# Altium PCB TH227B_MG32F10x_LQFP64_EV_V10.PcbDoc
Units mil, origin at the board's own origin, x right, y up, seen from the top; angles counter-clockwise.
Board outline 3031.5 x 2165.35 mil, 2 copper layers (Top Layer, Bottom Layer); 45 components, 67 nets, 247 pads, 62 vias.
Unrouted connection lines stored in the file: 6.
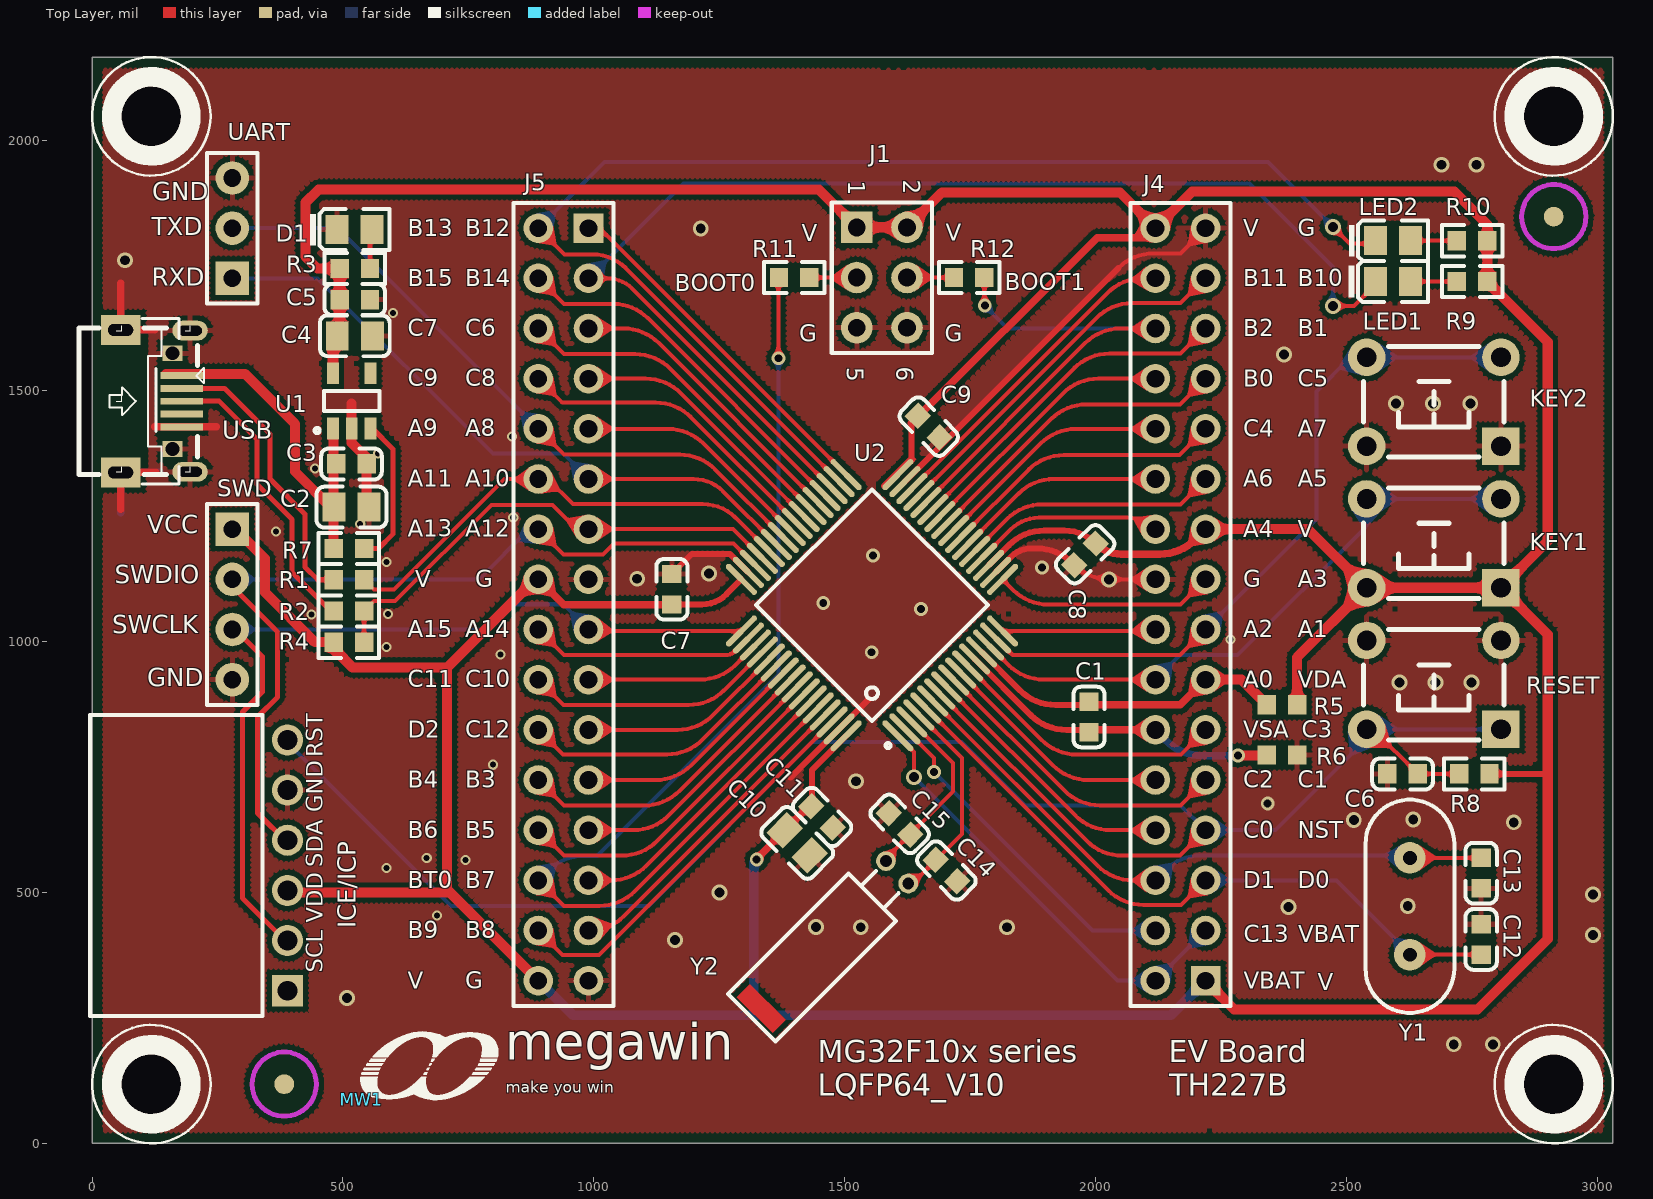
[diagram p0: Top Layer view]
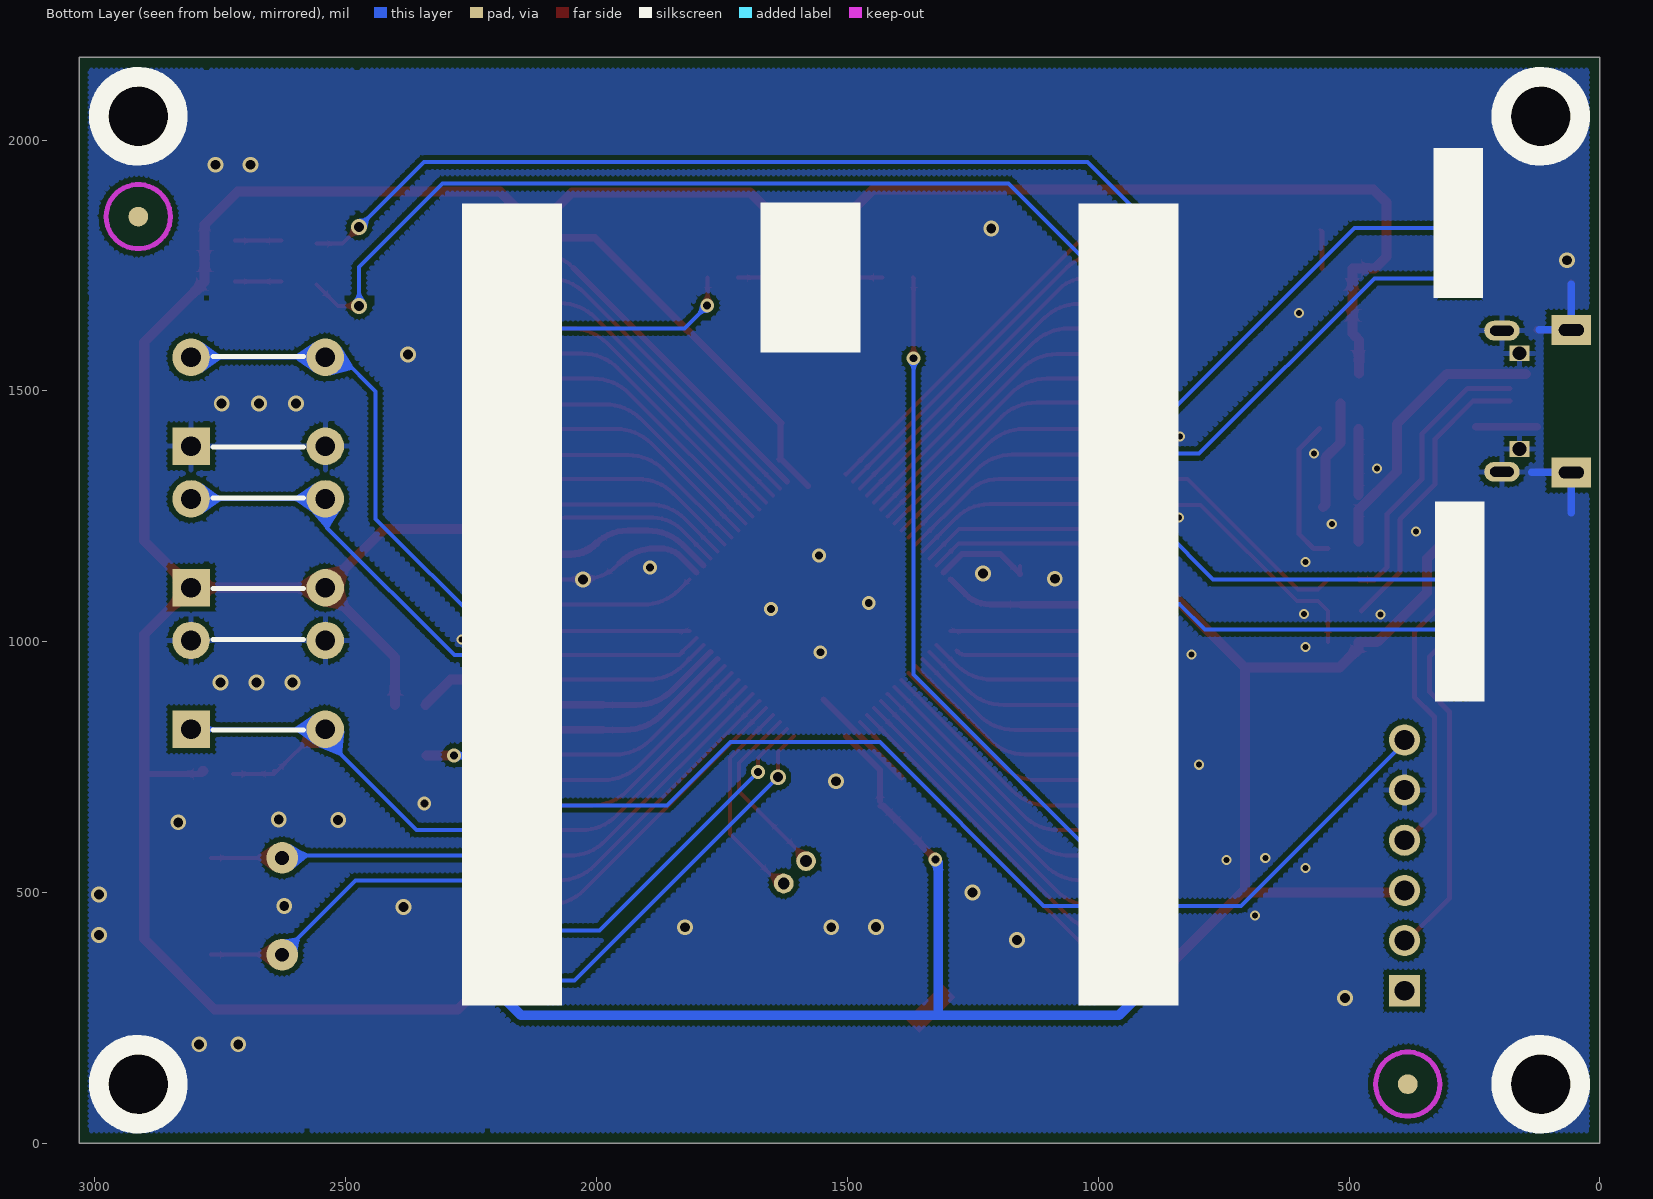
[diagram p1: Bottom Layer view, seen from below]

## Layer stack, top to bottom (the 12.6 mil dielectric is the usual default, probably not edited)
Top Layer: signal copper 1.4
Dielectric: dielectric 12.6, FR-4, Dk 4.8
Bottom Layer: signal copper 1.4

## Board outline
0,0 3031.5,0 3031.5,2165.35 0,2165.35

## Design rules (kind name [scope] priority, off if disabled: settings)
Clearance 10 [All] p1 off: gap=10
Clearance 6 [All] p2: gap=6
HoleSize [All] p1: absolutevalues=TRUE maxlimit=300 minlimit=1 maxpercent=80.000 minpercent=20.000
PolygonConnect "via Direct" [isvia] p1: connectstyle=Direct reliefconductorwidth=10 reliefentries=4 polygonreliefangle="90 Angle"
PolygonConnect "Relief 15" [isvia] p2: connectstyle=Relief reliefconductorwidth=15 reliefentries=4 polygonreliefangle="90 Angle"
RoomDefinition TH227B_MG32F10x_LQFP64_EV_V10 [InComponentClass('TH227B_MG32F10x_LQFP64_EV_V10')] p1: confinementstyle=ConfineIn formatcopy=TRUE lockcomponents=FALSE outline -120,-195 3150,-195 3150,2245 -120,2245
RoutingVias [All] p1: holewidth=15.75 width=27.56 viastyle="Through Hole" minholewidth=11.81 minwidth=23.62 maxholewidth=28 maxwidth=50
SilkscreenOverComponentPads SilkToSolderMaskClearance [IsPad] p1: minsilkscreentomaskgap=10
SolderMaskExpansion [All] p1: expansion=4
Width [All] p1: maxlimit=100 minlimit=6 preferedwidth=10 minimp=50.000000 maximp=50.000000 favimp=50.000000
26 further rules are at their usual default settings.

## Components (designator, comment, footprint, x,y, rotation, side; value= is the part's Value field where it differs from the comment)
C1 "0.1uF" 0603_C 1987.15,850 r270 top
C2 "10uF" 0805_C 517.15,1268.2 r0 top
C3 "0.1uF" 0603_C 517.15,1354.43 r0 top
C4 "10uF" 0805_C 523.8,1609.75 r0 top
C5 "0.1uF" 0603_C 523.8,1681.79 r0 top
C6 "0.1uF" 0603_C 2612.13,736.48 r180 top
C7 "0.1uF" 0603_C 1155.75,1104.62 r90 top
C8 "0.1uF" 0603_C 1979.37,1174.31 r225 top
C9 "0.1uF" 0603_C 1667.72,1428.74 r315 top
C10 "10uF" 0805_C 1405.44,599.08 r315 top
C11 "0.1uF" 0603_C 1455.12,650.65 r315 top
C12 "20pF" 0603_C 2768.9,406.56 r90 top
C13 "20pF" 0603_C 2768.9,538.84 r270 top
C14 "12pF" 0603_C 1702.79,543.96 r315 top
C15 "12pF" 0603_C 1609.81,636.94 r135 top
D1 "" 0805_LED_S1 523.23,1821.32 r0 top
ICE/ICP "" PS6P254F_90 389.61,304.31 r90 top (schematic designator J8)
J1 "CON3X2" HDR-3X2 1524.41,1825.85 r270 top (schematic designator JP1)
J4 "CON16X2" HDR2X16_MR#1 2219.53,324.31 r180 top (schematic designator P1)
J5 "CON16X2" HDR2X16_MR#2 989.61,1824.31 r180 top locked (schematic designator P2)
KEY1 "SW-PB4" "TSW DIP-6*6*6"#1 2674.41,1196.12 r180 top
KEY2 "SW-PB4" "TSW DIP-6*6*6"#1 2674.41,1478.21 r180 top
LED1 "" 0805_LED_S1 2593.21,1717.97 r0 top
LED2 "" 0805_LED_S1 2593.31,1799.27 r0 top (schematic designator LED1)
MW1 "MW-A4" MEGAWIN_3.4 537.8,86.83 r0 top
R1 "33" 0603_R 511.93,1123.53 r0 top
R2 "33" 0603_R 511.93,1061.32 r0 top
R3 "4.7k" 0603_R 523.8,1744 r0 top
R4 "1.5k" 0603_R 511.93,999.12 r180 top
R5 "0" 0603_R 2371.65,874.27 r180 top
R6 "0" 0603_R 2371.65,774.27 r180 top
R7 "0" 0603_R 511.93,1185.73 r0 top
R8 "10k" 0603_R 2755.12,736.48 r180 top
R9 "4.7k" 0603_R 2750.83,1717.97 r180 top
R10 "4.7k" 0603_R 2750.83,1799.27 r180 top
R11 "10k" 0603_R 1399.61,1725.85 r0 top
R12 "10k" 0603_R 1748.43,1725.85 r0 top
RESET "SW-PB4" "TSW DIP-6*6*6"#2 2674.41,914.04 r180 top
SWD "CON4" HDR-1X4 279.61,1224.31 r270 top
U1 "SPX3819M5-L-3-3" SOT-23-5 517.6,1479.96 r270 top
U2 "MG32F10x" LQFP64 1554.62,1072.77 r135 top locked
UART "CON3" HDR-1X3 279.61,1724.31 r90 top
USB "MICRO_USB" USB5-micro_B-建倚MRUSB-5B-D17xx- 167.96,1479.36 r270 top
Y1 "8MHz" LC-HC-49S 2626.69,472.7 r90 top
Y2 "32.768MHz" XTAL-3X8H 1604.67,540.4 r225 top

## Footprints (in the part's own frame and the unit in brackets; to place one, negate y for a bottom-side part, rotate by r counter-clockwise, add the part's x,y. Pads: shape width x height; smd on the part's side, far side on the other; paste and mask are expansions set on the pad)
0603_C [mm]
  rect 0.93x0.98 smd: 1(-0.77,0) 2(0.77,0)
  silkscreen extent -1.53,-0.79 1.54,0.79, body extent -0.8,-0.4 0.8,0.4, height 0.3
0603_R [mm]
  rect 0.93x0.98 smd: 1(-0.77,0) 2(0.77,0)
  silkscreen extent -1.53,-0.79 1.54,0.79, body extent -0.85,-0.4 0.85,0.4, height 0.56
0805_C [mm]
  rect 1.16x1.47 smd: 1(-0.89,0) 2(0.89,0)
  silkscreen extent -1.77,-1.04 1.77,1.04, body extent -1,-0.63 1,0.63, height 0.77
0805_LED_S1 [mm]
  rect 1.16x1.47 smd: 1(0.89,0) 2(-0.89,0)
  silkscreen extent -2.25,-1.04 1.77,1.03, body extent -1.01,-0.63 1.01,0.62, height 1.1
HDR2X16_MR#1 [mm] "Connector; Header; 16x2 Position"
  rect 1.5x1.5 hole 0.9: 1(0,0)
  round 1.5 hole 0.9: 2(2.54,0) 3(0,-2.54) 4(2.54,-2.54) 5(0,-5.08) 6(2.54,-5.08) 7(0,-7.62) 8(2.54,-7.62) 9(0,-10.16) 10(2.54,-10.16) 11(0,-12.7) 12(2.54,-12.7) 13(0,-15.24) 14(2.54,-15.24) 15(0,-17.78) 16(2.54,-17.78) 17(0,-20.32) 18(2.54,-20.32) 19(0,-22.86) 20(2.54,-22.86) 21(0,-25.4) 22(2.54,-25.4) 23(0,-27.94) 24(2.54,-27.94) 25(0,-30.48) 26(2.54,-30.48) 27(0,-33.02) 28(2.54,-33.02) 29(0,-35.56) 30(2.54,-35.56) 31(0,-38.1) 32(2.54,-38.1)
  silkscreen extent -1.27,-39.37 3.81,1.27
HDR2X16_MR#2 [mm] "Connector; Header; 16x2 Position"
  rect 1.5x1.5 hole 0.9: 1(0,0)
  round 1.5 hole 0.9: 2(2.54,0) 3(0,2.54) 4(2.54,2.54) 5(0,5.08) 6(2.54,5.08) 7(0,7.62) 8(2.54,7.62) 9(0,10.16) 10(2.54,10.16) 11(0,12.7) 12(2.54,12.7) 13(0,15.24) 14(2.54,15.24) 15(0,17.78) 16(2.54,17.78) 17(0,20.32) 18(2.54,20.32) 19(0,22.86) 20(2.54,22.86) 21(0,25.4) 22(2.54,25.4) 23(0,27.94) 24(2.54,27.94) 25(0,30.48) 26(2.54,30.48) 27(0,33.02) 28(2.54,33.02) 29(0,35.56) 30(2.54,35.56) 31(0,38.1) 32(2.54,38.1)
  silkscreen extent -1.27,-1.27 3.81,39.37
HDR-1X3 [mm] "齬渀ㄛ3褐"
  rect 1.7x1.7 hole 0.9: 1(0,0)
  round 1.7 hole 0.9: 2(2.54,0) 3(5.08,0)
  silkscreen extent -1.27,-1.27 6.35,1.27, body extent -1.27,-1.27 6.35,1.27, height 8.5
HDR-1X4 [mm] "齬渀ㄛ4褐"
  rect 1.7x1.7 hole 0.9: 1(0,0)
  round 1.7 hole 0.9: 2(2.54,0) 3(5.08,0) 4(7.62,0)
  silkscreen extent -1.27,-1.27 8.89,1.27, body extent -1.27,-1.27 8.89,1.27, height 8.5
HDR-3X2 [mm] "邧齬齬渀ㄛ3x2褐"
  rect 1.6x1.6 hole 0.9: 1(0,0)
  round 1.6 hole 0.9: 2(0,2.54) 3(2.54,0) 4(2.54,2.54) 5(5.08,0) 6(5.08,2.54)
  silkscreen extent -1.27,-1.27 6.35,3.81, body extent -1.27,-1.27 6.35,3.81, height 8.5
LC-HC-49S [mm]
  round 1.6 hole 0.7: 1(-2.45,0) 2(2.45,0)
  silkscreen extent -5.39,-2.25 5.39,2.25, body extent -5.39,-2.27 5.41,2.23, height 3.6
LQFP64 [mm]
  oval 2.1x0.3 smd: 1(-5.6,3.75) 2(-5.6,3.25) 3(-5.6,2.75) 4(-5.6,2.25) 5(-5.6,1.75) 6(-5.6,1.25) 7(-5.6,0.75) 8(-5.6,0.25) 9(-5.6,-0.25) 10(-5.6,-0.75) 11(-5.6,-1.25) 12(-5.6,-1.75) 13(-5.6,-2.25) 14(-5.6,-2.75) 15(-5.6,-3.25) 16(-5.6,-3.75) 33(5.6,-3.75) 34(5.6,-3.25) 35(5.6,-2.75) 36(5.6,-2.25) 37(5.6,-1.75) 38(5.6,-1.25) 39(5.6,-0.75) 40(5.6,-0.25) 41(5.6,0.25) 42(5.6,0.75) 43(5.6,1.25) 44(5.6,1.75) 45(5.6,2.25) 46(5.6,2.75) 47(5.6,3.25) 48(5.6,3.75)
  oval 0.3x2.1 smd: 17(-3.75,-5.6) 18(-3.25,-5.6) 19(-2.75,-5.6) 20(-2.25,-5.6) 21(-1.75,-5.6) 22(-1.25,-5.6) 23(-0.75,-5.6) 24(-0.25,-5.6) 25(0.25,-5.6) 26(0.75,-5.6) 27(1.25,-5.6) 28(1.75,-5.6) 29(2.25,-5.6) 30(2.75,-5.6) 31(3.25,-5.6) 32(3.75,-5.6) 49(3.75,5.6) 50(3.25,5.6) 51(2.75,5.6) 52(2.25,5.6) 53(1.75,5.6) 54(1.25,5.6) 55(0.75,5.6) 56(0.25,5.6) 57(-0.25,5.6) 58(-0.75,5.6) 59(-1.25,5.6) 60(-1.75,5.6) 61(-2.25,5.6) 62(-2.75,5.6) 63(-3.25,5.6) 64(-3.75,5.6)
  silkscreen extent -5.72,-4.15 4.15,4.57
MEGAWIN_3.4 [mil]
  silkscreen extent -2,0 272,135
PS6P254F_90 [mil]
  rect 62x62 hole 39.37: 1(0,0)
  round 62 hole 39.37: 2(100,0) 3(200,0) 4(300,0) 5(400,0) 6(500,0)
  silkscreen extent -50,50 550,394
SOT-23-5 [mm]
  rect 1.1x0.6 smd: 1(1.4,-0.95) 2(1.4,0) 3(1.4,0.95) 4(-1.4,0.95) 5(-1.4,-0.95)
  silkscreen extent -0.5,-1.87 1.62,1.4
"TSW DIP-6*6*6"#1 [mm] "6*6*6mm"
  rect 1.9x1.9 hole 1: 1(-3.4,2.25)
  round 1.9 hole 1: 2(3.4,2.25) 3(3.4,-2.25) 4(-3.4,-2.25)
  silkscreen extent -3.56,-2.79 3.56,2.79, body extent -4.11,-3 4.11,3, height 5.95
"TSW DIP-6*6*6"#2 [mm] "6*6*6mm"
  round 1.9 hole 1: 1(3.4,-2.25) 2(-3.4,-2.25) 4(3.4,2.25)
  rect 1.9x1.9 hole 1: 3(-3.4,2.25)
  silkscreen extent -3.56,-2.79 3.56,2.79, body extent -4.11,-3 4.11,3, height 5.95
USB5-micro_B-建倚MRUSB-5B-D17xx- [mm]
  rect 0.35x2.159 smd: 1(-1.3,0.279) 2(-0.65,0.279) 3(0,0.279) 4(0.65,0.279) 5(1.3,0.279)
  rect 0.8x1 hole 0.7: 5(-2.425,-0.19) 5(2.425,-0.19)
  oval 1x1.8 hole 0.5 slot 1.2 at 90 deg: 6(3.576,0.697) 9(-3.574,0.697)
  rect 1.5x2 hole 0.6 slot 1.27 at 90 deg: 7(3.607,-2.819) 8(-3.607,-2.819)
  silkscreen extent -4.19,-4.92 4.19,1.4, body extent -4,-5.61 4,-0.01, height 2.8
XTAL-3X8H [mm]
  round 1 hole 0.6: 1(0,-0.8) 2(0,0.8)
  silkscreen extent 0.7,-1.7 10.41,1.7

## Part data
C1 C2 C3 C4 C5 C6 C7 C8 C9 C10 C11 C12 C13 C14 C15: library part CAP, "Capacitor"
D1 LED1 LED2: library part LED_SC
ICE/ICP: library part CON6, "Connector"
MW1: library part MW_A4
R1 R2 R3 R4 R5 R6 R7 R8 R9 R10 R11 R12: library part RES1
SWD UART: "Connector"
U1: library part IC5_SPX3819M5-L-3-3
U2: library part IC64_MG32F10x
USB: library part USB_Micro
Y1 Y2: library part XTAL, "Crystal"

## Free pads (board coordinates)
  round 125.98 hole 118.11: 0(118.11,118.12) 0(118.12,2047.25) 0(2913.38,118.11) 0(2913.39,2047.24)
  round 39.37 smd mask+39.37: 0(383.11,118.12) 0(2913.39,1847.24)
  round 39.37 smd far side mask+39.37: 0(383.11,118.12) 0(2913.39,1847.24)

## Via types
v1: diameter 31.5, hole 19.68, Top Layer to Bottom Layer, tented both sides, 33 vias
v2: diameter 20, hole 12, Top Layer to Bottom Layer, tented both sides, 18 vias
v3: diameter 27.56, hole 15.75, Top Layer to Bottom Layer, tented both sides, 11 vias

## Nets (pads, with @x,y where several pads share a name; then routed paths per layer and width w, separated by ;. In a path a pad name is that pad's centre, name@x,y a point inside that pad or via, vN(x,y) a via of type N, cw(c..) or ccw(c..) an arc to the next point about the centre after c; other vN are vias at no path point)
BOOT0: J5.28 R11.1 U2.60 | length 2162.8
  Top Layer w8: J5.28@897.58,516.34 940.39,473.52 1011.39,473.52 ccw(c1011.39,573.52) 1082.1,502.81 U2.60 ; v3(1368.11,1565) 1368.11,1723.88 1367.72,1724.27 R11.1
  Bottom Layer w8: J5.28 909.1,543.8 cw(c979.81,473.09) 979.81,573.09 1006.24,573.09 1368.11,934.96 v3(1368.11,1565)
D+: R2.1 USB.3 | length 584.5
  Top Layer w10: USB.3@178.96,1479.35 253.36,1479.35 329.01,1403.7 329.01,1313.7 399.01,1243.7 399.01,1137.94 R2.1@475.62,1061.32
D-: R1.1 USB.2 | length 579.1
  Top Layer w8: R1.1 478.94,1123.53 480.28,1124.86 R1.1@481.61,1126.2
  Top Layer w10: USB.2 263.96,1504.95 354.61,1414.31 354.61,1324.31 424.61,1254.31 424.61,1148.54 449.62,1123.53 R1.1@478.94,1123.53
GND_POWER: C2.2 C3.2 C4.2 C5.2 C6.2 C7.2 C8.2 C9.2 C10.2 C11.2 C12.2 C13.2 C14.2 C15.2 D1.2 ICE/ICP.5 J1.5 J1.6 J4.18 J4.31 J5.15 J5.31 KEY2.1 KEY2.2 R6.1 RESET.1 RESET.2 SWD.4 U1.2 U2.18 U2.31 U2.47 U2.63 UART.3 USB.5 USB.6 USB.7 USB.8 USB.9 | length 2553.9
  Top Layer w8: J5.15@999.94,1124.31 J5.15@1010.57,1134.94 ; C7.2 C7.2@1155.75,1151.21 ; U2.47@1308.13,1138.19 U2.47 ; C8.2@1954.01,1156.8 C8.2 ccw(c2026.9,1221.83) v1(2026.9,1124.31) J4.18 ; 2045.53,1744.62 cw(c2116.24,1673.91) 2116.24,1773.91 2169.13,1773.91 J4.31
  Top Layer w12: C7.2 1195.8,1174.99 1271.32,1174.99 U2.47@1308.13,1138.19 ; 1391.75,728.95 1547.31,884.5 ; U2.31 2045.53,1744.62 ; U2.18 1832.25,1169.44 cw(c1872.44,1129.23) 1872.44,1186.08 1883.3,1186.08 cw(c1883.3,1086.08) C8.2@1954.01,1156.8
  Top Layer w15: 56.96,1264.49 USB.7 127.16,1337.36 ; 56.96,1714.12 USB.8 125.1,1621.36 ; 124.83,1428.17 247.15,1428.17
  Top Layer w20: 517.6,1474.31 517.6,1396.32 547.46,1366.45 C3.2 547.46,1272.93 C2.2
  Bottom Layer w15: 56.96,1257.16 USB.7 135.9,1337.36 ; 56.96,1712.16 USB.8 121.16,1621.36
  other v1: 2714.06,197.5 2792.09,197.5 508.15,290 1161.81,405.77 2991.73,415.22 1532.28,430.86 1824.02,430.86 1443.31,431.36 2385.04,471.52 2622.44,473.09 2991.73,496.32 1250.79,500.26 2833.86,640.02 2515,644.81 2633.47,645.93 1522.49,721.91 2606.3,918.41 2677.95,918.41 2749.61,918.41 1086.61,1125.46 1229.53,1136.09 2598.82,1475.06 2673.03,1475.06 2747.25,1475.06 2375.99,1572.31 65.63,1760.22 1213.39,1823.88 2689.75,1950.65 2759.45,1950.65
  other v2: 687.15,454.31 587.15,549.31 744.61,564.81 667.15,569.31 799.61,754.81 814.61,974.81 587.15,989.31 2269.61,1004.81 437.15,1054.31 589.61,1054.81 587.15,1159.31 367.15,1219.31 534.61,1234.81 839.61,1247.86 444.61,1344.81 569.61,1374.81 837.15,1409.31 599.61,1654.81
  other v3: 2343.31,677.82 1554,979 1652.36,1065.22 1457.48,1077.03 1893.31,1147.9 1556.69,1171.52
NetD1_1: D1.1 R3.2 | length 79
  Top Layer w6: D1.1@554.11,1817.16 D1.1
  Top Layer w10: R3.2 D1.1@554.11,1817.16
NetJ1_3: J1.3 R11.2 | length 94.5
  Top Layer w8: R11.2 J1.3
NetJ1_4: J1.4 R12.1 | length 93.7
  Top Layer w8: J1.4 R12.1
NetLED1_1: LED1.1 R9.2 | length 92.3
  Top Layer w7.87: LED1.1 R9.2
NetLED2_1: LED2.1 R10.2 | length 92.2
  Top Layer w8: LED2.1 R10.2
NetR7_2: R7.2 U1.3 | length 296.5
  Top Layer w10: R7.2 571.03,1185.73 599.61,1214.31 599.61,1384.31 U1.3@559.07,1424.84
NRST: C6.1 ICE/ICP.6 J4.7 R8.2 RESET.3 RESET.4 U2.7 | length 3743.6
  Top Layer w8: U2.7 1982.82,602.81 ccw(c2053.53,673.52) 2053.53,573.52 2168.74,573.52 J4.7@2207.78,612.56 ; RESET.4 2553.47,825.45 C6.1 R8.2 ; C6.1@2640.79,741.99 C6.1@2642.44,741.99
  Bottom Layer w8: ICE/ICP.6@388.94,799.78 715.21,473.52 1108.82,473.52 1435.3,800 1733.15,800 1859.24,673.91 2169.92,673.91 J4.7 2359,624.31 2540.55,805.86 RESET.4 RESET.3
PA0: J4.14 KEY1.3 KEY1.4 U2.14 | length 1252.4
  Top Layer w8: U2.14 1826.9,953.6 ccw(c1897.62,1024.31) 1897.62,924.31 J4.14
  Bottom Layer w8: J4.14 2168.71,973.49 2283.46,973.49 2537.11,1227.13 2537.11,1284.71 KEY1.3@2537.11,1311.98 ; KEY1.3 KEY1.4
PA1: J4.15 KEY2.3 KEY2.4 U2.15 | length 1416.2
  Top Layer w8: U2.15 1835.21,973.13 2168.35,973.13 J4.15
  Bottom Layer w8: J4.15 2440.16,1244.94 2440.16,1499.08 2507.88,1566.79 KEY2.3 KEY2.4
PA2: J4.16 U2.16 | length 305.9
  Top Layer w8: U2.16 2116.48,1021.26 J4.16
PA3: J4.17 U2.17 | length 442
  Top Layer w8: U2.17 1835.98,1103.2 ccw(c1906.69,1173.91) 1906.69,1073.91 2169.13,1073.91 J4.17
PA4: J4.20 U2.20 | length 382.6
  Top Layer w8: U2.20 1830.47,1223.34 ; 1830.49,1223.36 cw(c1887.94,1165.86) 1887.94,1247.14 2064.4,1247.14 cw(c2064.4,1169.18) 2119.49,1224.34 cw(c2064.4,1169.18) J4.20
PA5: J4.21 U2.21 | length 515.8
  Top Layer w8: U2.21 1823.92,1244.62 cw(c1894.63,1173.91) 1894.63,1273.91 2169.13,1273.91 J4.21
PA6: J4.22 U2.22 | length 423.9
  Top Layer w8: U2.22 1846.47,1295.02 cw(c1917.18,1224.31) 1917.18,1324.31 J4.22
PA7: J4.23 U2.23 | length 573.5
  Top Layer w8: U2.23 1866.27,1342.66 cw(c1936.98,1271.94) 1936.98,1371.94 2167.16,1371.94 J4.23
PA8: J5.9 U2.41 | length 481.8
  Top Layer w8: J5.9 1147.74,1424.31 cw(c1147.74,1324.31) 1218.45,1395.02 U2.41
PA9: J5.10 U2.42 UART.2 | length 1349.3
  Top Layer w8: J5.10 941.18,1372.73 1171.47,1372.73 cw(c1171.47,1272.73) 1242.19,1343.44 U2.42
  Bottom Layer w8: UART.2 489.61,1824.31 J5.10
PA10: J5.11 U2.43 UART.1 | length 1300.4
  Top Layer w8: J5.11 1198.67,1324.31 cw(c1198.67,1240.27) 1258.09,1299.71 U2.43
  Bottom Layer w8: UART.1 449.18,1724.31 798.82,1374.67 939.25,1374.67 J5.11
PA11: J5.12 R1.2 U2.44 | length 963.1
  Top Layer w8: R1.2 561.97,1103.8 601.71,1103.8 822.22,1324.31 J5.12 908.25,1324.31 958.25,1274.31 1217.3,1274.31 cw(c1217.3,1181.73) 1282.76,1247.19 U2.44
PA12: J5.13 R2.2 R4.1 U2.45 | length 987.8
  Top Layer w8: R4.1 R2.2 561.89,1080.97 604.33,1080.97 796.06,1272.7 917.72,1272.7 966.11,1224.31 J5.13 1277.81,1224.31 U2.45
PA13: ICE/ICP.4 J5.14 SWD.2 U2.46 | length 1719.3
  Top Layer w8: J5.14 939.61,1174.31 1018.5,1174.31 1040.14,1195.95 1278.33,1195.95 U2.46
  Top Layer w10: SWD.2@280,1109.31 369.61,1019.7 369.61,889.61 330,850 330,658.73 ICE/ICP.4@388.94,599.78
  Bottom Layer w8: SWD.2 771.29,1124.31 871.29,1224.31 J5.14
PA14: ICE/ICP.2 J5.17 SWD.3 U2.49 | length 1765.4
  Top Layer w8: J5.17 ccw(c996.95,1031.65) 996.95,1021.26 U2.49
  Top Layer w10: SWD.3@280,1030 339.61,970.39 339.61,899.61 300,860 300,488.73 ICE/ICP.2@388.94,399.78
  Bottom Layer w8: SWD.3 787.46,1024.31 837.82,1074.67 939.25,1074.67 J5.17
PA15: J5.18 U2.50 | length 400.4
  Top Layer w8: J5.18@901.12,1012.79 940.39,973.52 1262.38,973.52 ccw(c1262.38,1002.59) U2.50@1282.94,982.04
PB0: J4.26 U2.26 | length 539.4
  Top Layer w8: U2.26 1935.11,1495.02 cw(c2005.82,1424.31) 2005.82,1524.31 J4.26
PB1: J4.27 U2.27 | length 689
  Top Layer w8: U2.27 1957.28,1545.02 cw(c2027.99,1474.31) 2027.99,1574.31 2169.53,1574.31 J4.27
PB2: J4.28 R12.2 U2.28 | length 1014
  Top Layer w8: U2.28 1979.44,1595.02 cw(c2050.15,1524.31) 2050.15,1624.31 J4.28 ; R12.2 1778.74,1681.25 ccw(c1790.84,1681.25) 1782.28,1672.7 v3(1779.53,1669.94)
  Bottom Layer w8: v3(1779.53,1669.94) 1795.87,1653.6 1825.16,1624.31 1866.59,1624.31 J4.28
PB3: J5.23 U2.55 | length 472.3
  Top Layer w8: J5.23 1122.98,724.31 ccw(c1122.98,824.31) 1193.69,753.6 U2.55
PB4: J5.24 U2.56 | length 606
  Top Layer w8: J5.24@901.32,712.6 940.39,673.52 1100.03,673.52 ccw(c1100.03,773.52) 1170.75,702.81 U2.56
PB5: J5.25 U2.57 | length 530.1
  Top Layer w8: J5.25 1078.66,624.31 ccw(c1078.66,724.31) 1149.37,653.6 U2.57
PB6: J5.26 U2.58 | length 669.6
  Top Layer w8: J5.26@897.18,616.73 940.39,573.52 1055.71,573.52 ccw(c1055.71,673.52) 1126.42,602.81 U2.58
PB7: J5.27 U2.59 | length 587.8
  Top Layer w8: J5.27 1034.34,524.31 ccw(c1034.34,624.31) 1105.05,553.6 U2.59
PB8: J5.29 U2.61 | length 645.5
  Top Layer w8: J5.29 990.01,424.31 ccw(c990.01,524.31) 1060.73,453.6 U2.61
PB9: J5.30 U2.62 | length 798.1
  Top Layer w8: J5.30 938.06,375.85 1010.82,375.85 U2.62
PB10: J4.29 U2.29 | length 746.7
  Top Layer w8: U2.29 2001.99,1645.41 cw(c2072.7,1574.7) 2072.7,1674.7 2169.92,1674.7 J4.29
PB11: J4.30 U2.30 | length 654.9
  Top Layer w8: U2.30 2023.76,1695.02 cw(c2094.47,1624.31) 2094.47,1724.31 J4.30
PB12: J5.1 U2.33 | length 716.4
  Top Layer w8: J5.1 cw(c989.61,1770.55) 1018.69,1815.76 cw(c989.61,1770.55) 1027.61,1808.57 U2.33@1502.26,1333.92 ; U2.33 U2.33@1502.26,1333.92 ; U2.33@1503.98,1333.92 U2.33@1502.26,1333.92
PB13: J5.2 LED2.2 U2.34 | length 2595.2
  Top Layer w8: J5.2 941.97,1771.94 997.37,1771.94 cw(c997.37,1677.74) 1063.99,1744.35 U2.34 ; v1(2473.23,1826.64) 2506.5,1793.37 LED2.2@2558.27,1793.37
  Bottom Layer w8: J5.2 1021.07,1955.77 2344.1,1955.77 v1(2473.23,1826.64)
PB14: J5.3 LED1.2 U2.35 | length 2467.6
  Top Layer w8: J5.3 1027.14,1724.31 cw(c1027.14,1654.17) 1076.74,1703.77 U2.35 ; v1(2473.23,1669.16) 2515.25,1669.16 LED1.2@2558.17,1712.07
  Bottom Layer w8: J5.3 1178.55,1913.25 2307.09,1913.25 2473.23,1747.11 v1(2473.23,1669.16)
PB15: J5.4 U2.36 | length 747
  Top Layer w8: J5.4 940.79,1673.13 1039.71,1673.13 cw(c1039.71,1576.97) 1107.66,1645 ; 1107.7,1644.96 U2.36
PC0: J4.8 U2.8 | length 530
  Top Layer w8: U2.8 1959.87,653.6 ccw(c2030.58,724.31) 2030.58,624.31 J4.8
PC1: J4.9 U2.9 | length 622.1
  Top Layer w8: U2.9 1938.1,703.2 ccw(c2008.81,773.91) 2008.81,673.91 2169.13,673.91 J4.9
PC2: J4.10 U2.10 | length 472.2
  Top Layer w8: U2.10 1915.55,753.6 ccw(c1986.26,824.31) 1986.26,724.31 J4.10
PC3: J4.11 U2.11 | length 563.4
  Top Layer w8: U2.11 1892.6,804.38 ccw(c1963.31,875.09) 1963.31,775.09 2170.31,775.09 J4.11
PC4: J4.24 U2.24 | length 481.7
  Top Layer w8: U2.24 1890.79,1395.02 cw(c1961.5,1324.31) 1961.5,1424.31 J4.24
PC5: J4.25 U2.25 | length 631.2
  Top Layer w8: U2.25 1911.77,1443.84 cw(c1982.48,1373.13) 1982.48,1473.13 2168.35,1473.13 J4.25
PC6: J5.5 U2.37 | length 597.2
  Top Layer w8: J5.5 1059.09,1624.31 cw(c1059.09,1524.31) 1129.81,1595.02 U2.37
PC7: J5.6 U2.38 | length 689.1
  Top Layer w8: J5.6 940.79,1573.13 1082.44,1573.13 cw(c1082.44,1473.13) 1153.15,1543.84 U2.38
PC8: J5.7 U2.39 | length 539.5
  Top Layer w8: J5.7 1103.42,1524.31 cw(c1103.42,1424.31) 1174.13,1495.02 U2.39
PC9: J5.8 U2.40 | length 631.4
  Top Layer w8: J5.8 937.24,1476.67 1123.21,1476.67 cw(c1123.21,1376.67) 1193.93,1447.38 U2.40
PC10: J5.19 U2.51 | length 356.9
  Top Layer w8: J5.19 1211.63,924.31 ccw(c1211.63,1024.31) 1282.34,953.6 U2.51
PC11: J5.20 U2.52 | length 506.8
  Top Layer w8: J5.20 940,873.91 1189.07,873.91 ccw(c1189.07,973.91) 1259.78,903.2 U2.52
PC12: J5.21 U2.53 | length 414.6
  Top Layer w8: J5.21 1167.3,824.31 ccw(c1167.3,924.31) 1238.02,853.6 U2.53
PC13: J4.4 U2.2 | length 682.6
  Top Layer w8: U2.2 1678.15,768.29 v3(1678.15,740)
  Bottom Layer w8: v3(1678.15,740) 1993.84,424.31 J4.4
PC14: C15.1 U2.3 Y2.1 | length 366.9
  Top Layer w8: Y2.1 1582.4,568.24 1715.93,701.76 1715.93,758.34 U2.3
PC15: C14.1 U2.4 Y2.2 | length 421.1
  Top Layer w8: Y2.2 1635.58,518.13 1733.93,616.47 1733.93,768.18 U2.4
PD0: C12.1 J4.5 U2.5 Y1.1 | length 1348
  Top Layer w8: U2.5 2025.17,504.78 ; 2025.17,504.78 ccw(c2095.88,575.49) 2095.88,475.49 2170.71,475.49 J4.5 ; Y1.1 C12.1
  Bottom Layer w8: J4.5 2480.32,524.31 2626.69,377.93 Y1.1
PD1: C13.1 J4.6 U2.6 Y1.2 | length 1263.4
  Top Layer w8: U2.6 2004.19,553.6 ccw(c2074.91,624.31) 2074.91,524.31 J4.6 ; Y1.2 C13.1
  Bottom Layer w8: J4.6 2140.2,544.98 cw(c2210.92,474.27) 2210.92,574.27 2625.51,574.27 Y1.2@2633.39,582.15
PD2: J5.22 U2.54 | length 563.2
  Top Layer w8: J5.22 938.42,775.49 1146.33,775.49 ccw(c1146.33,875.49) 1217.04,804.78 U2.54
VBAT: J4.2 J4.3 U2.1 | length 886.6
  Top Layer w8: U2.1 1638.15,780.45 1638.15,760.45 v1(1638.15,730)
  Bottom Layer w8: v1(1638.15,730) 2043.84,324.31 J4.2 J4.3
VCC: C4.1 C5.1 C7.1 C8.1 C9.1 C10.1 C11.1 ICE/ICP.3 J1.1 J1.2 J4.1 J4.19 J4.32 J5.16 J5.32 KEY1.1 KEY1.2 R3.1 R4.2 R5.1 R8.1 R9.1 R10.1 SWD.1 U1.5 U2.19 U2.32 U2.48 U2.64 | length 11917.9
  Top Layer w8: C7.1@1154.72,1073.88 ccw(c1154.72,1075.34) C7.1 ; J4.19@2199.18,1203.96 J4.19
  Top Layer w11.81: J5.16@883.46,1124.31 J5.16 ; C11.1@1428.89,672.09 C11.1 ; R8.1 2896.75,736.48 2901.56,731.67
  Top Layer w12: C7.1 1215.74,1074.31 ccw(c1215.74,1143.12) 1264.4,1094.46 U2.48@1294.27,1124.33 ; C11.1@1435.41,682.12 1435.41,744.77 U2.64 ; U2.32@1578.15,1310 1633.15,1365 1633.15,1435 ; U2.19 1827.2,1192.23 cw(c1897.91,1121.52) 1897.91,1221.52 1938.58,1221.52 cw(c1938.58,1133.52) C8.1
  Top Layer w15: J5.16 940.03,1073.88 C7.1@1154.72,1073.88 ; v3@1323.61,566.81 C10.1 C11.1@1428.89,672.09 ; 1633.15,1435 2003.15,1805 J4.32@2128.15,1805 ; C8.1 ccw(c2051.69,1246.63) 2051.69,1174.67 2128.47,1174.67 ccw(c2128.47,1274.67) J4.19@2199.18,1203.96
  Top Layer w20: SWD.1@280,1230 344.61,1165.39 344.61,1098.54 444.03,999.12 R4.2 ; ICE/ICP.3@388.94,499.78 714.13,499.78 ; R4.2@469.03,999.12 R4.2 ; U1.5 480.19,1601.18 C4.1 493.48,1614.47 C5.1 R3.1 448.98,1744 425.2,1767.78 425.2,1875.06 451.18,1901.05 1449.21,1901.05 J1.1 J1.2 1693.7,1895.14 2048.69,1895.14 J4.32@2117.98,1825.85 ; J5.16@883.46,1124.31 707.45,948.29 ; J5.32 714.13,499.78 ; J4.32@2098.91,1825.85 J4.32@2117.98,1825.85 ; J4.1 2276.65,267.19 2761.38,267.19 2901.56,407.36 2901.56,731.67 2901.56,1014.25 KEY1.1 ; J4.19 2423.79,1224.31 KEY1.2 ; R5.1 2401.97,968.96 KEY1.2 ; R8.1@2783.78,741.99 R8.1@2785.44,741.99 ; R4.2 481.61,986.14 519.47,948.29 707.45,948.29 ; 707.45,948.29 707.45,506.47 714.13,499.78 ; J4.32@2117.98,1825.85 J4.32 2192.77,1897.55 2715.31,1897.55 2781.14,1831.71 R9.1 2784.1,1715.02 2785.63,1713.49 2901.56,1597.56 2901.56,1200.83 KEY1.1 ; KEY1.2 KEY1.1
  Bottom Layer w19.68: SWD.1@273.15,1230 SWD.1@280,1230 ; J5.32 958.54,255.38 2150.6,255.38 J4.1 ; 1318.9,259.71 1318.9,559.71 v3(1324.8,565.61)
VCC5: C2.1 C3.1 R7.1 U1.1 USB.1 | length 697.7
  Top Layer w11.81: U1.1 U1.1@480.88,1424.15
  Top Layer w20: USB.1@147.15,1534 304.91,1534 404.61,1434.31 404.61,1339.31 480.88,1263.03 R7.1@480.88,1200.06 ; C2.1@480.88,1291.99 480.88,1354.31 U1.1@480.88,1424.15
VDDA: C1.1 J4.13 R5.2 U2.13 | length 650.2
  Top Layer w8: R5.2@2340.32,874.27 R5.2
  Top Layer w12: U2.13 1849.46,903.2 ccw(c1920.17,973.91) 1920.17,873.91 C1.1@1987.8,873.91
  Top Layer w15: C1.1@1987.8,873.91 2169.13,873.91 J4.13
  Top Layer w20: J4.13 2291.31,924.31 R5.2
VSSA: C1.2 J4.12 R6.2 U2.12 | length 648.4
  Top Layer w8: R6.2@2338.49,773.09 ccw(c2338.49,777.13) R6.2
  Top Layer w12: U2.12 1871.23,853.6 ccw(c1941.94,924.31) 1941.94,824.31 C1.2@1982.64,824.31
  Top Layer w15: C1.2@1987.8,824.31 J4.12
  Top Layer w20: v3(2284.25,773.09) R6.2@2338.49,773.09
  Bottom Layer w15: J4.12 2141.45,802.38 ccw(c2212.16,873.09) 2212.16,773.09 v3(2284.25,773.09)
pads on no net: ICE/ICP.1 U1.4 USB.4

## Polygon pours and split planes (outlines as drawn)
no net on Bottom Layer "Bottom Layer-No Net 3" (solid, pour order 68): 886.61,2239.23
GND_POWER on Bottom Layer "Top Layer-GND" (hatched 90Degree grid 10 track 10, remove dead copper, pour order 0): 25,2140 3010,2140 3010,25 25,25
GND_POWER on Top Layer "Top Layer-GND" (hatched 90Degree grid 10 track 10, remove dead copper, pour order 0): 25,2140 3010,2140 3010,25 25,25

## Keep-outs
Top Layer:
  circle w10: c383.11,118.12 r64.06
  circle w10: c2913.7,1847.24 r64.06
Bottom Layer:
  circle w10: c2913.39,1847.24 r64.06
  circle w10: c383.11,118.12 r64.06

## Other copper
Top Layer:
  region: 1284.51,291.64 1356.34,219.82 1383.06,246.54 1311.24,318.37
  pour cut-out: 324.05,118.12 ccw(c383.11,118.12) 383.11,59.06 ccw(c383.11,118.12) 442.16,118.12 ccw(c383.11,118.12) 383.11,177.17 ccw(c383.11,118.12)
  pour cut-out: 324.05,118.12 ccw(c383.11,118.12) 383.11,59.06 ccw(c383.11,118.12) 442.16,118.12 ccw(c383.11,118.12) 383.11,177.17 ccw(c383.11,118.12)
  pour cut-out: 2849.33,1847.24 ccw(c2913.39,1847.24) 2913.39,1783.18 ccw(c2913.39,1847.24) 2977.44,1847.24 ccw(c2913.39,1847.24) 2913.39,1911.29 ccw(c2913.39,1847.24)
  pour cut-out: -5.06,1337.32 116.78,1337.32 116.78,1619.91 -4.69,1619.91
Bottom Layer:
  pour cut-out: 319.05,118.12 ccw(c383.11,118.12) 383.11,54.06 ccw(c383.11,118.12) 447.16,118.12 ccw(c383.11,118.12) 383.11,182.17 ccw(c383.11,118.12)
  pour cut-out: 2849.33,1847.24 ccw(c2913.39,1847.24) 2913.39,1783.18 ccw(c2913.39,1847.24) 2977.44,1847.24 ccw(c2913.39,1847.24) 2913.39,1911.29 ccw(c2913.39,1847.24)
  pour cut-out: -5.06,1337.32 116.78,1337.32 116.78,1619.91 -4.69,1619.91
  region net PA14: 300.11,1001.06 300.11,1047.56 321.81,1028.4 321.81,1020.21
  region net PA13: 300.11,1101.06 300.11,1147.56 321.81,1128.4 321.81,1120.21

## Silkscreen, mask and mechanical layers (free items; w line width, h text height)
Top Overlay:
  circle w5: c118.11,118.12 r118.11
  circle w5: c2913.38,118.11 r118.11
  circle w5: c2913.39,2047.24 r118.11
  circle w5: c118.12,2047.25 r118.11
  circle w39.37: c118.12,2047.25 r78.74
  circle w39.37: c118.11,118.12 r78.74
  circle w39.37: c2913.39,2047.24 r78.74
  circle w39.37: c2913.38,118.11 r78.74
  text "GND" at 120,1880 h35.43
  text "TXD" at 118.94,1809.78 h35.43
  text "B13" at 628.98,1808.56 h33.46
  text "B12" at 743.94,1808.56 h33.46
  text "V" at 2294.72,1808.56 h33.46
  text "G" at 2403.39,1808.56 h33.46
  text "V" at 1701.18,1799.08 h33.46
  text "V" at 1414.17,1797.9 h33.46
  text "RXD" at 118.94,1709.78 h35.43
  text "B15" at 628.98,1708.56 h33.46
  text "B14" at 743.94,1708.56 h33.46
  text "B11" at 2294.72,1708.56 h33.46
  text "B10" at 2403.39,1708.56 h33.46
  text "BOOT1" at 1819.69,1700.26 h33.46
  text "BOOT0" at 1161.81,1698.68 h33.46
  text "C7" at 628.98,1609.31 h33.46
  text "C6" at 743.94,1609.31 h33.46
  text "B2" at 2294.72,1608.56 h33.46
  text "B1" at 2403.39,1608.56 h33.46
  text "G" at 1409.45,1598.29 h33.46
  text "G" at 1700,1598.29 h33.46
  text "C9" at 628.98,1509.26 h33.46
  text "C8" at 743.94,1509.26 h33.46
  text "B0" at 2294.72,1508.56 h33.46
  text "C5" at 2403.39,1508.56 h33.46
  text "A9" at 628.98,1409.2 h33.46
  text "A8" at 743.94,1409.2 h33.46
  text "C4" at 2294.72,1408.56 h33.46
  text "A7" at 2403.39,1408.56 h33.46
  text "A11" at 628.98,1309.14 h33.46
  text "A10" at 743.94,1309.14 h33.46
  text "A6" at 2294.72,1308.56 h33.46
  text "A5" at 2403.39,1308.56 h33.46
  text "VCC" at 110,1216.5 h35.43
  text "A13" at 628.98,1209.08 h33.46
  text "A12" at 743.94,1209.08 h33.46
  text "A4" at 2294.72,1208.56 h33.46
  text "V" at 2403.39,1208.56 h33.46
  text "SWDIO" at 45,1116.5 h35.43
  text "V" at 644.72,1109.02 h33.46
  text "G" at 763.62,1109.02 h33.46
  text "G" at 2294.72,1108.56 h33.46
  text "A3" at 2403.39,1108.56 h33.46
  text "SWCLK" at 40,1016.5 h35.43
  text "A15" at 628.98,1008.97 h33.46
  text "A14" at 743.94,1008.97 h33.46
  text "A2" at 2294.72,1008.56 h33.46
  text "A1" at 2403.39,1008.56 h33.46
  text "GND" at 110,911.5 h35.43
  text "C11" at 628.98,908.91 h33.46
  text "C10" at 743.94,908.91 h33.46
  text "A0" at 2294.72,908.56 h33.46
  text "VDA" at 2403.39,908.56 h33.46
  text "D2" at 628.98,808.85 h33.46
  text "C12" at 743.94,808.85 h33.46
  text "VSA" at 2294.72,808.56 h33.46
  text "C3" at 2411.02,808.53 h33.46
  text "RST" at 460,770 h33 r90
  text "B4" at 628.98,708.79 h33.46
  text "B3" at 743.94,708.79 h33.46
  text "C2" at 2294.72,708.56 h33.46
  text "C1" at 2403.39,708.56 h33.46
  text "GND" at 460,660 h33 r90
  text "B6" at 628.98,608.74 h33.46
  text "B5" at 743.94,608.74 h33.46
  text "C0" at 2294.72,608.56 h33.46
  text "NST" at 2403.39,608.56 h33.46
  text "SDA" at 460,550 h33 r90
  text "BT0" at 628.98,508.68 h33.46
  text "B7" at 743.94,508.68 h33.46
  text "D1" at 2294.72,508.56 h33.46
  text "D0" at 2403.39,508.56 h33.46
  text "VDD" at 460,440 h33 r90
  text "B9" at 628.98,408.62 h33.46
  text "B8" at 743.94,408.62 h33.46
  text "C13" at 2295.51,401.08 h33.46
  text "VBAT" at 2404.17,401.08 h33.46
  text "SCL" at 460,340 h33 r90
  text "V" at 628.98,308.56 h33.46
  text "G" at 743.94,308.56 h33.46
  text "VBAT" at 2296.06,308.13 h33.46
  text "V" at 2443.54,305.81 h33.46
  text "MG32F10x series" at 1446.06,161.64 h43.31
  text "EV Board" at 2146.06,161.64 h43.31
  text "LQFP64_V10" at 1446.85,95.49 h43.31
  text "TH227B" at 2146.85,95.49 h43.31
Bottom Overlay:
  circle w39.37: c118.12,2047.25 r78.74
  circle w39.37: c118.11,118.12 r78.74
  circle w39.37: c2913.39,2047.24 r78.74
  circle w39.37: c2913.38,118.11 r78.74
  rectangle: 2069.29,275.06 2268.5,1873.88
  rectangle: 1474.41,1576.64 1673.62,1875.06
  rectangle: 839.76,274.67 1039.37,1873.88
  rectangle: 230,880.79 328.82,1279.21
  rectangle: 233.29,1685.29 332.11,1984.51
  lines w19.68: 857.68,374.27 1021.85,374.27 ; 857.68,474.27 1021.85,474.27 ; 857.68,574.27 1021.85,574.27 ; 857.68,674.27 1021.85,674.27 ; 857.68,774.27 1021.85,774.27 ; 857.68,874.27 1021.85,874.27 ; 857.68,974.27 1021.85,974.27 ; 857.68,1074.27 1021.85,1074.27 ; 857.68,1174.27 1021.85,1174.27 ; 857.68,1274.27 1021.85,1274.27 ; 857.68,1374.27 1021.85,1374.27 ; 857.68,1474.27 1021.85,1474.27 ; 857.68,1574.27 1021.85,1574.27 ; 857.68,1674.27 1021.85,1674.27 ; 857.68,1774.27 1021.85,1774.27 ; 939.76,293.17 939.76,1856.16 ; 1491.93,1676.64 1656.1,1676.64 ; 1491.93,1776.64 1656.1,1776.64 ; 1574.02,1589.63 1574.02,1858.53 ; 2087.6,374.27 2251.77,374.27 ; 2087.6,474.27 2251.77,474.27 ; 2087.6,574.27 2251.77,574.27 ; 2087.6,674.27 2251.77,674.27 ; 2087.6,774.27 2251.77,774.27 ; 2087.6,874.27 2251.77,874.27 ; 2087.6,974.27 2251.77,974.27 ; 2087.6,1074.27 2251.77,1074.27 ; 2087.6,1174.27 2251.77,1174.27 ; 2087.6,1274.27 2251.77,1274.27 ; 2087.6,1374.27 2251.77,1374.27 ; 2087.6,1474.27 2251.77,1474.27 ; 2087.6,1574.27 2251.77,1574.27 ; 2087.6,1674.27 2251.77,1674.27 ; 2087.6,1774.27 2251.77,1774.27 ; 2169.68,293.17 2169.69,1856.16
Top Solder:
  region: 1311.24,318.37 1284.66,291.79 1356.51,219.94 1383.09,246.52
Mechanical 1:
  the board outline again, w8.19

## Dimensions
0,0 to 3031.5,0 on Top Overlay
3031.5,0 to 3031.5,2165.35 on Top Overlay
